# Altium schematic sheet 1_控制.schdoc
size 309 x 223 mm; Symbol: Sheet-Symbol_A4; Device: Sheet-Symbol_A4; Company: 嘉立创EDA; Version: V1.0; Page Size: A4; @Project Name: 辉光管时钟成品; @Page Count: 2; @Update Date: 2024-08-01; @Create Date: 2024-01-13; @Schematic Name: 电源+控制部分; @Page No: 1; @Page Name: 控制
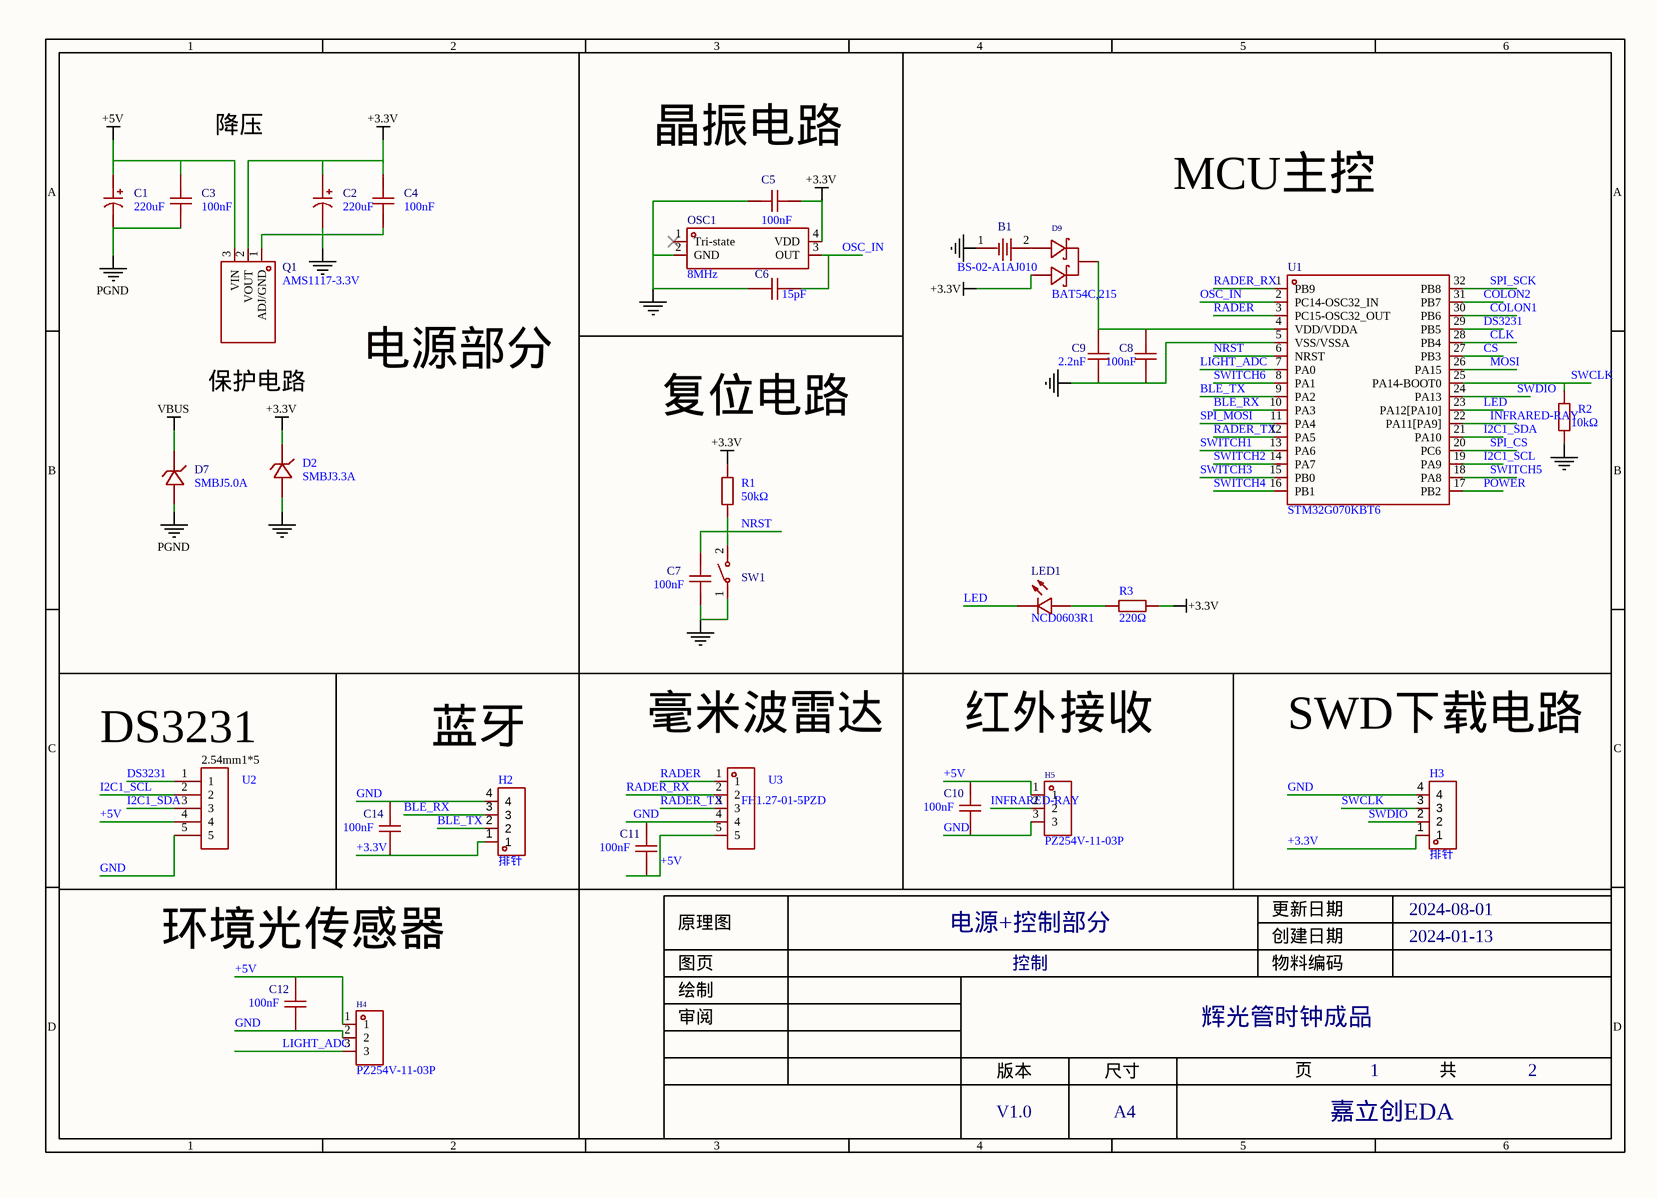
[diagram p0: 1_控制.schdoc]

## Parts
B1  BS-02-A1AJ010  [BAT-TH_BS-02-A1AJ010]
C1  220uF  [CAP-SMD_BD6.3-L6.6-W6.6-FD]
C2  220uF  [CAP-SMD_BD6.3-L6.6-W6.6-FD]
C3  100nF  [C0603]
C4  100nF  [C0603]
C5  100nF  [C0603]
C6  15pF  [C0603]
C7  100nF  [C0603]
C8  100nF  [C0603]
C9  2.2nF  [C0603]
C10  100nF  [C0603]
C11  100nF  [C0603]
C12  100nF  [C0603]
C14  100nF  [C0603]
D2  SMBJ3.3A  [SMB_L4.6-W3.6-LS5.3-RD]
D7  SMBJ5.0A  [SMB_L4.4-W3.6-LS5.3-RD]
D9  BAT54C,215  [SOT-23-3_L2.9-W1.6-P1.90-LS2.8-BR]
H2  排针  [SIP-2.54MM-4P-CJT-H8.54]
H3  排针  [SIP-2.54MM-4P-CJT-H8.54]
H4  PZ254V-11-03P  [HDR-TH_3P-P2.54-V-M]
H5  PZ254V-11-03P  [HDR-TH_3P-P2.54-V-M]
LED1  NCD0603R1  [LED0603-RD_RED]
OSC1  8MHz  [OSC-SMD_4P-L3.2-W2.5-BL-1]
Q1  AMS1117-3.3V  [SOT-89-3_L4.5-W2.5-P1.50-LS4.2-BR]
R1  50kΩ  [r0603]
R2  10kΩ  [r0603]
R3  220Ω  [r0603]
SW1  TS-1088R-02026  [SW-SMD_L3.9-W3.0-P4.45]  (value not drawn)
U1  STM32G070KBT6  [LQFP-32_L7.0-W7.0-P0.80-LS9.0-BL]
U2  (no value)  [2.54mm1*5]
U3  FH1.27-01-5PZD  [HDR-TH_5P-P1.27-V-M]

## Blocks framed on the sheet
电源部分: C1-C4 D2 D7 Q1
晶振电路: C5 C6 OSC1
MCU主控: B1 C8 C9 D9 LED1 R2 R3 U1
复位电路: C7 R1 SW1
DS3231: U2
蓝牙: C14 H2
毫米波雷达: C11 U3
SWD下载电路: H3
红外接收: C10 H5
环境光传感器: C12 H4

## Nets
+3.3V: C2.1 C4.2 C5.1 C14.1 D2.1 D9.1(A) H2.1 H3.1 OSC1.4(VDD) Q1.2(VOUT) R1.2 R3.1
+5V: C1.1 C3.2 C10.2 C11.1 C12.2 H4.1 H5.1 Q1.3(VIN) U2.4 U3.5
GND: B1.1 C2.2 C4.1 C5.2 C6.2 C7.1 C8.1 C9.1 C10.1 C11.2 C12.1 C14.2 D2.2 H2.4 H3.4 H4.2 H5.3 OSC1.2(GND) Q1.1(ADJ/GND) R2.1 SW1.1 U1.5(VSS/VSSA) U2.5 U3.4
PGND: C1.2 C3.1 D7.2(A)
VBUS: D7.1(C)
BLE_RX: H2.3 U1.10(PA3)
BLE_TX: H2.2 U1.9(PA2)
CLK: U1.28(PB4)
COLON1: U1.30(PB6)
COLON2: U1.31(PB7)
CS: U1.27(PB3)
DS3231: U1.29(PB5) U2.1
I2C1_SCL: U1.19(PA9) U2.2
I2C1_SDA: U1.21(PA10) U2.3
INFRARED-RAY: H5.2 U1.22(PA11[PA9])
LED: LED1.1(K) U1.23(PA12[PA10])
LIGHT_ADC: H4.3 U1.7(PA0)
MOSI: U1.26(PA15)
NRST: C7.2 R1.1 SW1.2 U1.6(NRST)
OSC_IN: C6.1 OSC1.3(OUT) U1.2(PC14-OSC32_IN)
POWER: U1.17(PB2)
RADER: U1.3(PC15-OSC32_OUT) U3.1
RADER_RX: U1.1(PB9) U3.2
RADER_TX: U1.12(PA5) U3.3
SPI_CS: U1.20(PC6)
SPI_MOSI: U1.11(PA4)
SPI_SCK: U1.32(PB8)
SWCLK: H3.3 R2.2 U1.25(PA14-BOOT0)
SWDIO: H3.2 U1.24(PA13)
SWITCH1: U1.13(PA6)
SWITCH2: U1.14(PA7)
SWITCH3: U1.15(PB0)
SWITCH4: U1.16(PB1)
SWITCH5: U1.18(PA8)
SWITCH6: U1.8(PA1)
NetB1_2: B1.2 D9.2(A)
NetC8_2: C8.2 C9.2 D9.3(K) U1.4(VDD/VDDA)
NetLED1_2: LED1.2(A) R3.2

Not connected (* = marked no-connect by the designer): OSC1 1(Tri-state)*

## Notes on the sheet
- 降压
- 保护电路

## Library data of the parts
B1 = BS-02-A1AJ010: Manufacturer: MYOUNG(美阳); Add into BOM: yes; Connector Type: 电池底座; Battery Type: CR2032
C1 C2 = RVT220UF10V67RV0037: Manufacturer: KNSCHA(科尼盛); Add into BOM: yes; Tolerance: ±20%; Rated Voltage: 10V; Ripple Current: 69mA@120Hz; φD: 6.3mm; L: 5.4mm; Lifetime @ Temp: 2000hrs@105℃
C3-C12 C14 = CC0603KRX7R9BB104: Manufacturer: YAGEO(国巨); Add into BOM: yes; Tolerance: ±10%; Voltage Rated: 50V; Temperature Coefficient: X7R
D2 = SMBJ3.3A_C362089: Manufacturer: JKSEMI(金开盛); Add into BOM: yes; Unidirectional Channels: 1; Bidirectional Channels: 0; Reverse Stand-Off Voltage (Vrwm): 3.3V; Breakdown Voltage: 4.1V; Maximum Clamping Voltage: 7.3V; Peak Pulse Power Dissipation (Ppp)@10/1000us: 600W
D7 = SMBJ5.0A_C726811: Manufacturer: TWGMC(台湾迪嘉); Add into BOM: yes
D9 = BAT54C,215: Manufacturer: Nexperia(安世); Add into BOM: yes; Diode Configuration: 1对共阴极; Reverse Voltage (Vr): 30V; Average Rectified Current (Io): 200mA; Forward Voltage (Vf@If): 800mV@100mA; Reverse Leakage Current (Ir): 2uA@25V
H2 H3 = 排针: Add into BOM: yes
H4 H5 = PZ254V-11-03P: Manufacturer: XFCN(兴飞); Symbol: PZ254V-11-03P_C2937625; Add into BOM: yes; Pitch: 2.54mm; Pin Structure: 1x3P; Circluar Pins/Square Pins: 方针; Current Rating (Max): 3A; Voltage Rating (Max): 250V
LED1 = NCD0603R1_C84263: Manufacturer: 国星光电; Symbol: FC-DA1608HRK-620D; Add into BOM: yes; Emitted Color: 红色; Forward Voltage (VF): 1.6V~2.6V; Forward Current: 20mA; Power Dissipation: 65mW; Lens Color: 无色透明; Dominant Wavelength: 615nm~630nm; Luminous Intensity: 80mcd~220mcd; Viewing Angle: 130°
OSC1 = OT2EL4C4JI-111OLP-8M: Manufacturer: YXC(扬兴晶振); Add into BOM: yes; Supply Voltage: 1.8V~3.3V
Q1 = AMS1117-3.3V_C5120796: Manufacturer: MSKSEMI(美森科); Add into BOM: yes; Output Type: 固定; Maximum Input Voltage: 18V; Output Voltage: 3.3V; MAX Output Current: 1A; Dropout Voltage: 1.4V@(1A); standby current: 12mA; Output Polarity: 正极; Number of Outputs: 1
R1-R3 = 0805W8F1002T5E_C17414: Manufacturer: UNI-ROYAL(厚声); Symbol: 电阻; Add into BOM: yes; Tolerance: ±1%; Power(Watts): 125mW; Temperature Coefficient: ±100ppm/℃; Overload Voltage (Max): 150V
SW1 = TS-1088R-02026: Manufacturer: XUNPU(讯普); Add into BOM: yes; Circuit: 单刀单掷; Actuator Style: 圆形按钮; Switch Length: 3.9mm; Switch Width: 2.93mm; Switch Height: 2mm; Contact Current: 50mA; Voltage Rating (DC): 12V
U1 = STM32G070KBT6: Manufacturer: ST(意法半导体); Add into BOM: yes; CPU Core: ARM Cortex-M0; CPU Maximum Speed: 64MHz; Operating Voltage Range: 2V~3.6V; Program Storage Size: 128KB; Program Memory Type: FLASH; RAM Size: 36KB; GPIO Ports Number: 29; ADC (Bit): 12bit; Peripheral/Function: DMA；PWM; Internal Oscillator: 有
U2 = 2.54mm1*5: Add into BOM: yes
U3 = FH1.27-01-5PZD: Manufacturer: XUNPU(讯普); Add into BOM: yes; Pins Structure: 1x5P; Pitch: 1.27mm; Number of PINs Per Row: 5; Current Rating (Max): 1A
